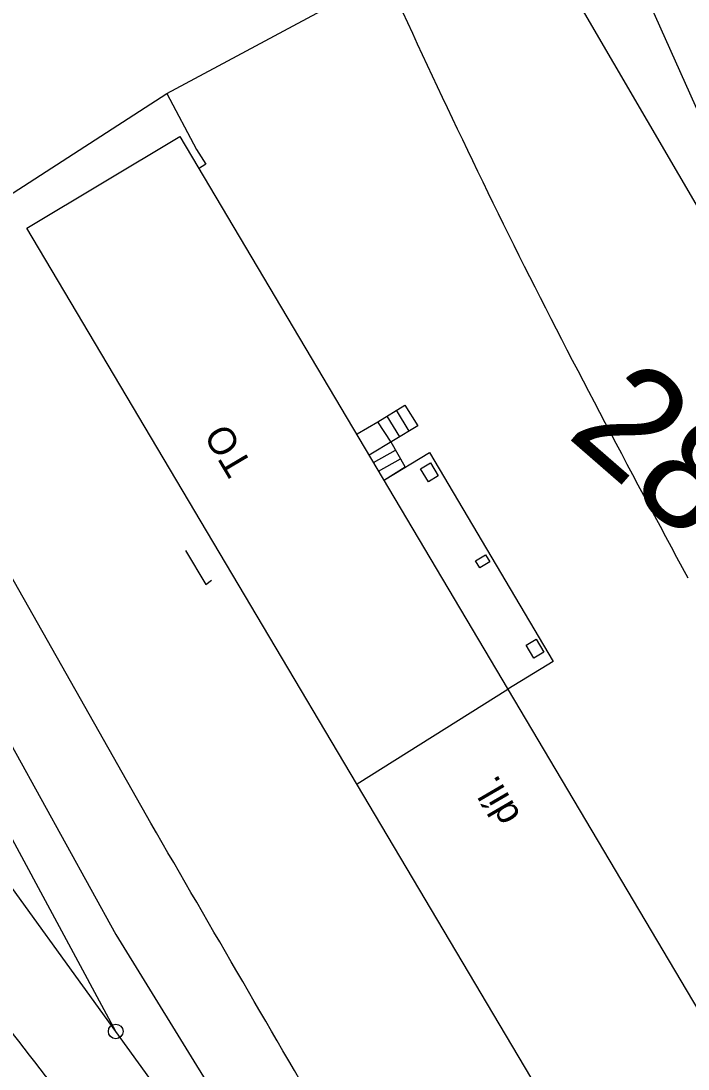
# Model space of a CAD drawing. Extents: x -496570 to -495506, y -1089156 to -1088046.
# Drawn here: x -496034.6 to -495998.4, y -1088542 to -1088485 of the extents above; entities that cross this region are included whole.
import ezdxf

# ---------------------------------------------------------------- set-up
doc = ezdxf.new("R2010")
doc.units = 0
for name, color, linetype in [('11', 7, 'Continuous'), ('14', 7, 'Continuous'), ('27', 7, 'Continuous'), ('39', 7, 'Continuous'), ('54', 7, 'Continuous'), ('PŮVODNÍ_NÁVRH', 7, 'Continuous'), ('SEE', 7, 'Continuous')]:
    doc.layers.add(name, color=color, linetype=linetype)

msp = doc.modelspace()

# ---------------------------------------------------------------- linework, layer by layer
at = {"layer": '14'}
for points in [[(-495984.212, -1088520.604), (-495987.937, -1088512.179), (-495995.163, -1088495.835), (-496007.326, -1088468.627), (-496015.768, -1088449.655), (-496024.81, -1088429.42), (-496048.198, -1088376.798)], [(-496029.461, -1088539.924), (-496035.456, -1088528.788), (-496050.622, -1088500.683), (-496060.148, -1088482.537), (-496074.283, -1088455.273)], [(-495987.937, -1088512.179), (-495997.014, -1088496.474), (-496009.447, -1088475.159), (-496012.25, -1088470.334)], [(-496027.558, -1088528.593), (-496035.765, -1088514.119), (-496040.307, -1088506.105), (-496049.124, -1088490.548), (-496059.857, -1088471.5)], [(-496011.29, -1088565.037), (-496022.068, -1088550.141), (-496029.461, -1088539.924), (-496036.884, -1088529.665), (-496046.952, -1088515.759), (-496054.33, -1088505.532), (-496061.713, -1088495.299), (-496072.458, -1088480.37)]]:
    msp.add_lwpolyline(points, dxfattribs=at)
for points in [[(-495998.352, -1088515.291), (-496007.808, -1088497.191), (-496016.532, -1088478.726)], [(-496012.573, -1088566.09), (-496028.822, -1088547.857), (-496038.151, -1088535.934), (-496051.597, -1088517.251)], [(-495994.179, -1088583.585), (-496001.925, -1088571.928), (-496007.411, -1088562.975), (-496027.558, -1088528.593)]]:
    msp.add_spline(points, degree=3, dxfattribs=at)
at = {"layer": '27'}
for points in [[(-496029.461, -1088539.924), (-496035.456, -1088528.788)], [(-496022.068, -1088550.141), (-496029.461, -1088539.924), (-496036.884, -1088529.665)]]:
    msp.add_lwpolyline(points, dxfattribs=at)
msp.add_circle((-496029.461, -1088539.924), 0.4, dxfattribs=at)
at = {"layer": '39'}
for p, q in [((-496013.753, -1088505.875), (-496013.031, -1088507.003)), ((-496014.719, -1088506.474), (-496014.035, -1088507.609)), ((-496014.212, -1088506.159), (-496013.524, -1088507.301)), ((-496013.031, -1088507.003), (-496015.686, -1088508.604)), ((-496015.451, -1088509), (-496014.249, -1088508.325)), ((-496015.173, -1088509.469), (-496013.982, -1088508.8))]:
    msp.add_line(p, q, dxfattribs=at)
for points in [[(-495974.045, -1088579.399), (-495982.418, -1088584.284), (-495997.256, -1088558.819), (-496003.517, -1088548.12), (-496034.293, -1088496.252), (-496025.968, -1088491.27), (-495995.168, -1088543.196), (-495974.045, -1088579.399)], [(-496016.329, -1088507.444), (-496015.219, -1088506.783), (-496013.753, -1088505.875)], [(-496014.847, -1088509.931), (-496013.736, -1088509.239), (-496014.495, -1088507.886), (-496015.219, -1088506.783)], [(-496014.847, -1088509.931), (-496012.409, -1088508.46), (-496005.683, -1088519.815), (-496008.141, -1088521.324)], [(-496012.888, -1088509.345), (-496012.347, -1088509.021), (-496011.926, -1088509.725), (-496012.466, -1088510.048), (-496012.888, -1088509.345)], [(-496025.667, -1088513.785), (-496024.571, -1088515.627), (-496024.258, -1088515.392)], [(-496009.901, -1088514.332), (-496009.361, -1088514.008), (-496009.124, -1088514.403), (-496009.665, -1088514.727), (-496009.901, -1088514.332)], [(-496007.153, -1088518.922), (-496006.612, -1088518.598), (-496006.191, -1088519.302), (-496006.732, -1088519.626), (-496007.153, -1088518.922)], [(-496016.343, -1088526.457), (-496008.141, -1088521.324)]]:
    msp.add_lwpolyline(points, dxfattribs=at)
at = {"layer": '54'}
msp.add_lwpolyline([(-496037.63, -1088519.866), (-496029.46, -1088534.646), (-496022.279, -1088546.306), (-496021.845, -1088547.068)], dxfattribs=at)
at = {"layer": 'PŮVODNÍ_NÁVRH'}
msp.add_lwpolyline([(-496046.99, -1088501.65), (-496042.82, -1088499.36), (-496035.34, -1088494.54), (-496026.68, -1088488.94), (-496017.01, -1088483.74), (-496015.61, -1088482.89), (-496011.64, -1088481.25), (-496002.63, -1088476.82)], dxfattribs=at)
at = {"layer": 'SEE'}
for points in [[(-496051.62, -1088524.39), (-496051.01, -1088524.72), (-496048.89, -1088527.16), (-496044.09, -1088523.58), (-496040.8, -1088521.19), (-496037.7, -1088519.67), (-496041.89, -1088512.27), (-496046.41, -1088504), (-496046.99, -1088501.65), (-496042.82, -1088499.36), (-496035.34, -1088494.54), (-496026.68, -1088488.94), (-496017.01, -1088483.74), (-496015.61, -1088482.89), (-496011.64, -1088481.25), (-496002.63, -1088476.82), (-496002.82, -1088476.02), (-496008.96, -1088461.03), (-496015.33, -1088446.34), (-496027.34, -1088417), (-496033.98, -1088400.73), (-496038.24, -1088391.07)], [(-496026.68, -1088488.94), (-496025.07, -1088491.98), (-496024.56, -1088492.78), (-496024.955, -1088493.03)]]:
    msp.add_lwpolyline(points, dxfattribs=at)

# ---------------------------------------------------------------- texts
at = {"layer": '11'}
msp.add_text('289,7', height=6, rotation=318.9438, dxfattribs=at).set_placement((-496005.026, -1088507.532))
at = {"layer": '39'}
for s, rotation, p in [('TO', 120.6829, (-496021.998, -1088509.161)), ('díl.', 120.2286, (-496007.421, -1088528.192))]:
    msp.add_text(s, height=1.5, rotation=rotation, dxfattribs=at).set_placement(p)

doc.saveas('drawing.dxf')
